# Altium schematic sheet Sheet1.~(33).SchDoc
size A3; SheetNumber: 1; SheetTotal: 1
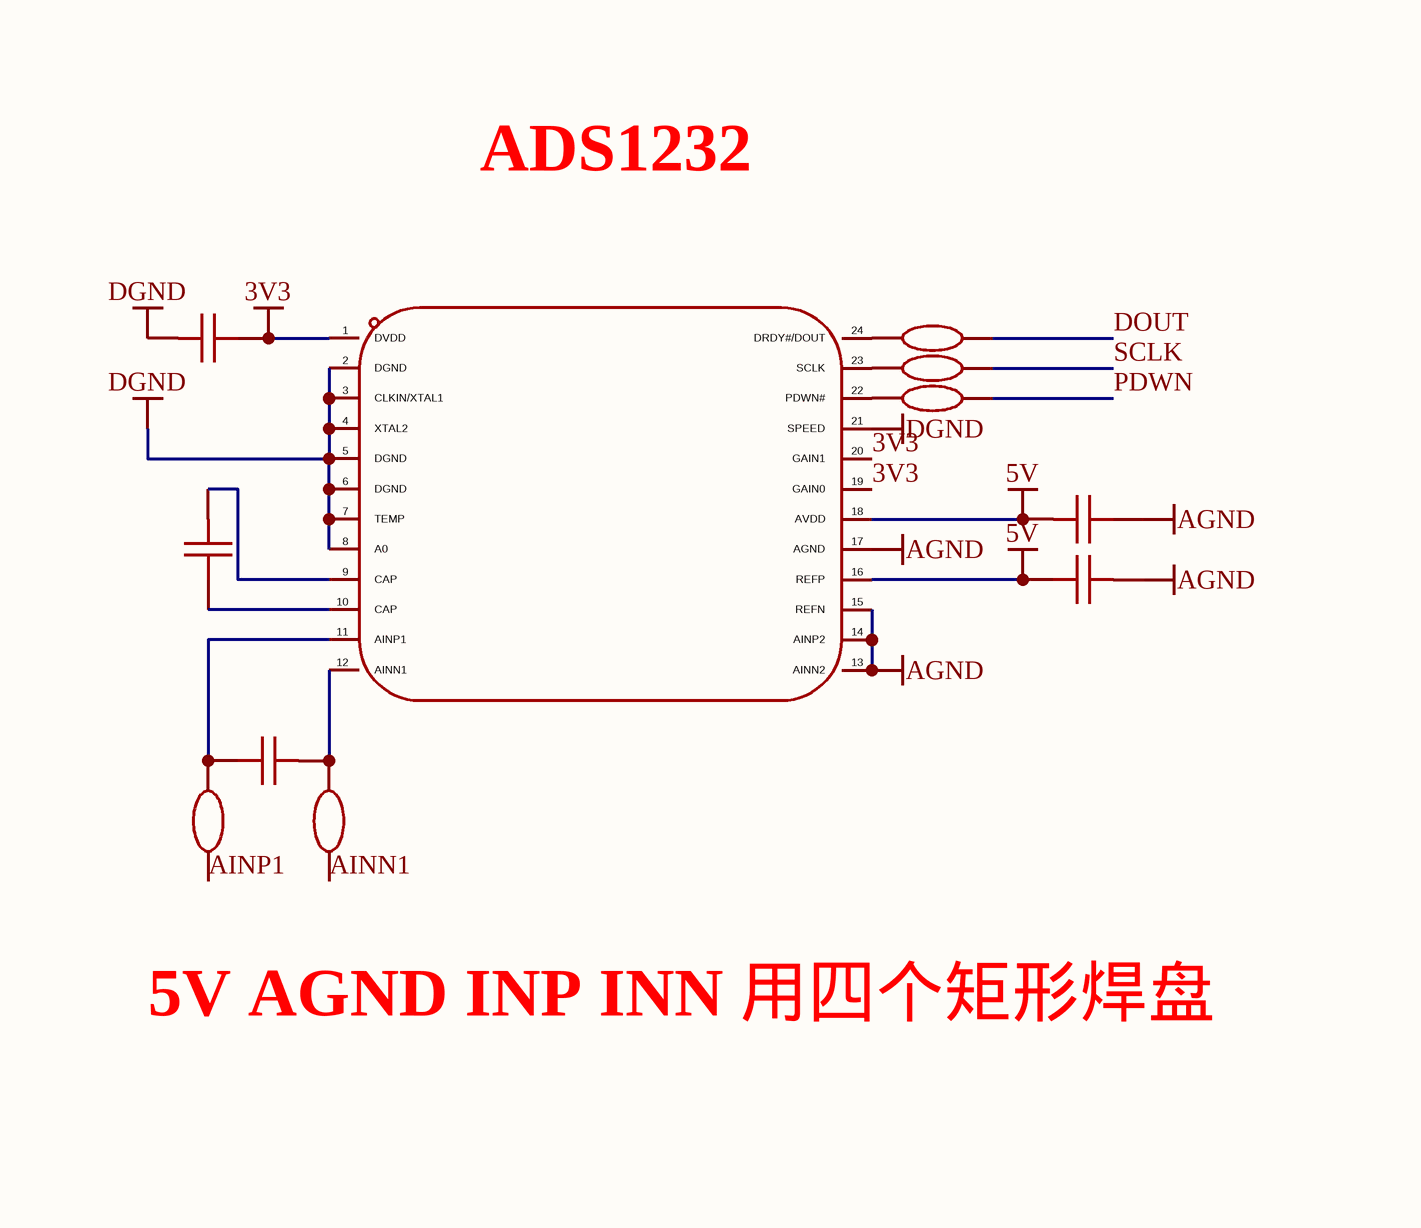
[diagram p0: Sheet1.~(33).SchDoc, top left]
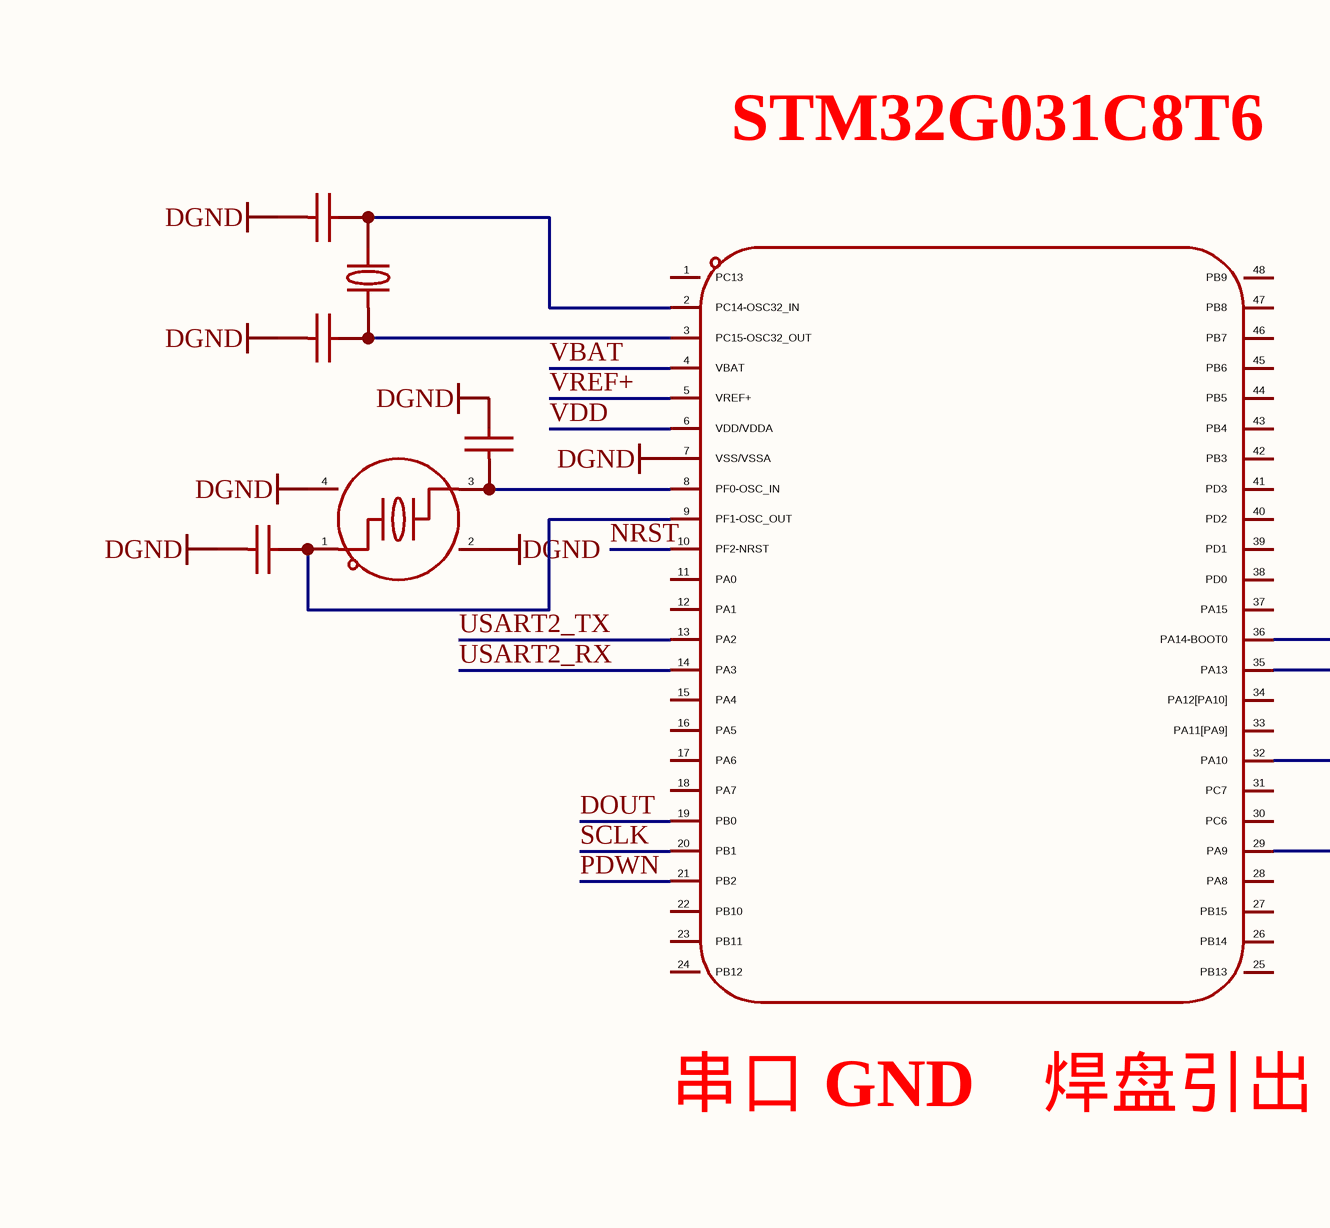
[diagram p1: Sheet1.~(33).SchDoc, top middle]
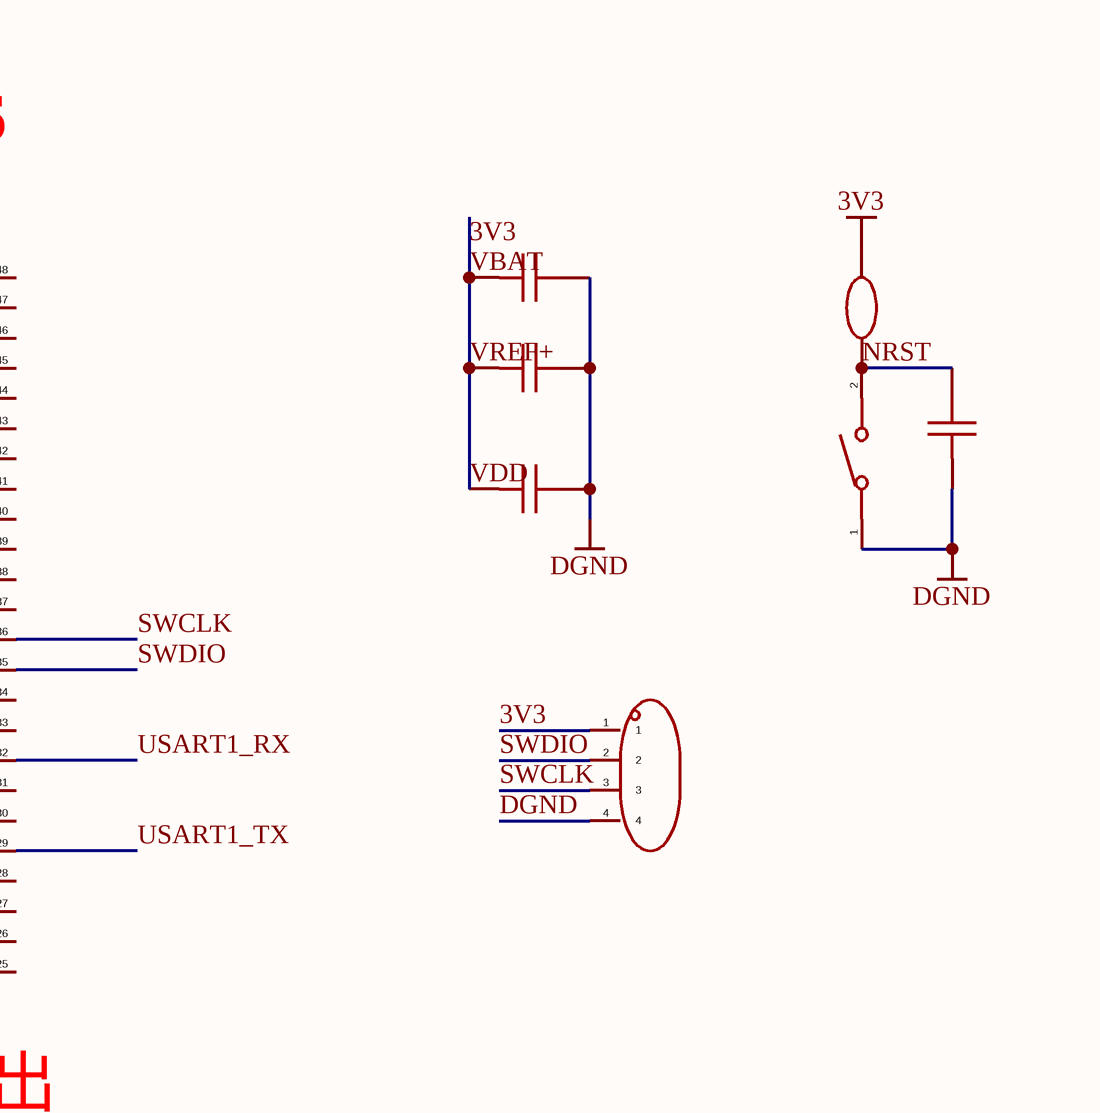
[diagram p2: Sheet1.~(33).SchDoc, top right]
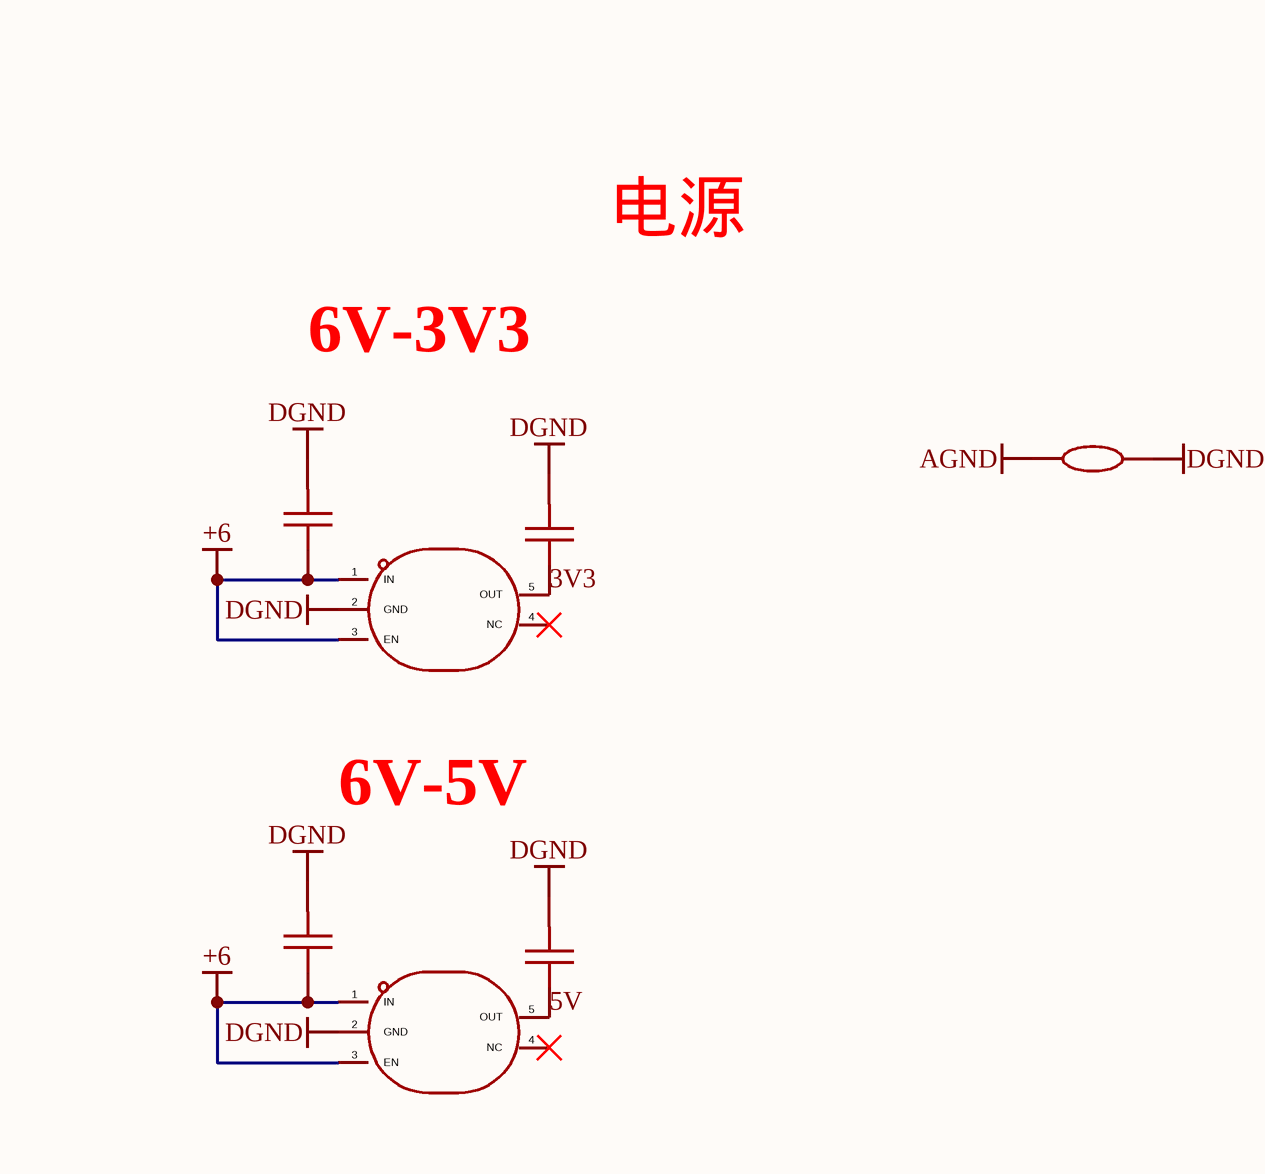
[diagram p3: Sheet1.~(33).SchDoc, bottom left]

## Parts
(Parts that share a designator on the sheet are numbered #1, #2 ... from top to bottom, then left to right.)
C?#1  cga0603x7r104k500jt  [C0603]  (value not drawn)
C?#2  cga0603x7r104k500jt  [C0603]  (value not drawn)
C?#3  cga0603x7r104k500jt  [C0603]  (value not drawn)
C?#4  cga0603x7r104k500jt  [C0603]  (value not drawn)
C?#5  cga0603x7r104k500jt  [C0603]  (value not drawn)
C?#6  cga0603x7r104k500jt  [C0603]  (value not drawn)
C?#7  fcc0603b103k500ct  [C0603]  (value not drawn)
C?#8  cga0603x5r105k500jt  [C0603]  (value not drawn)
C?#9  cga0603x5r105k500jt  [C0603]  (value not drawn)
C??#1  cc0402jrnpo9bn220  [C0402]  (value not drawn)
C??#2  cc0402jrnpo9bn220  [C0402]  (value not drawn)
C??#3  cc0402jrnpo9bn180  [C0402]  (value not drawn)
C??#4  cga0603x7r104k500jt  [C0603]  (value not drawn)
C??#5  cc0402jrnpo9bn180  [C0402]  (value not drawn)
C??#6  fcc0603b103k500ct  [C0603]  (value not drawn)
C??#7  cga0603x5r105k500jt  [C0603]  (value not drawn)
C??#8  cga0603x5r105k500jt  [C0603]  (value not drawn)
R?  0603waf470jt5e  [R0603]  (value not drawn)
R??#1  frc0603f1002ts  [R0603]  (value not drawn)
R??#2  0603waf470jt5e  [R0603]  (value not drawn)
R??#3  0603waf470jt5e  [R0603]  (value not drawn)
R??#4  frc0603f1000ts  [R0603]  (value not drawn)
R??#5  frc0603f1000ts  [R0603]  (value not drawn)
R??#6  0603waf0000t5e  [R0603]  (value not drawn)
SW??  ts-1088-ar02016  [SW-SMD_L3.9-W3.0-P4.45]  (value not drawn)
U??#1  fc31m2-32.768-ntlnndtl  [CRYSTAL-SMD_L3.2-W1.5]  (value not drawn)
U??#2  ads1232ipwr  [TSSOP-24_L7.8-W4.4-P0.65-LS6.4-BL]  (value not drawn)
U??#3  stm32g031c8t6  [LQFP-48_L7.0-W7.0-P0.50-LS9.0-BL]  (value not drawn)
U??#4  hx pz2.54-1x4p zz  [HDR-TH_4P-P2.54-V-M]  (value not drawn)
U??#5  tps7a2033pdbvr  [SOT-23-5_L2.9-W1.6-P0.95-LS2.8-BR]  (value not drawn)
U??#6  tps7a2050pdbvr  [SOT-23-5_L2.9-W1.6-P0.95-LS2.8-BR]  (value not drawn)
X??  x32258mob4si  [CRYSTAL-SMD_4P-L3.2-W2.5-BL]  (value not drawn)

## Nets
3V3: C?#1.2 C?#2.1 C?#3.2 C?#5.2 C?#8.1 R??#1.2 U??#2.1(DVDD) U??#2.19(GAIN0) U??#2.20(GAIN1) U??#3.4(VBAT) U??#3.5(VREF+) U??#3.6(VDD/VDDA) U??#4.1 U??#5.5(OUT)  [also labelled VBAT, VDD, VREF+]
5V: C?#6.2 C?#7.1 C?#9.1 U??#2.16(REFP) U??#2.18(AVDD) U??#6.5(OUT)
+6: C??#7.1 C??#8.1 U??#5.1(IN) U??#5.3(EN) U??#6.1(IN) U??#6.3(EN)
AGND: C?#6.1 C?#7.2 R??#6.1 U??#2.13(AINN2) U??#2.14(AINP2) U??#2.15(REFN) U??#2.17(AGND)
DGND: C?#1.1 C?#2.2 C?#3.1 C?#4.2 C?#5.1 C?#8.2 C?#9.2 C??#1.1 C??#2.1 C??#3.2 C??#5.1 C??#7.2 C??#8.2 R??#6.2 SW??.1 U??#2.2(DGND) U??#2.3(CLKIN/XTAL1) U??#2.4(XTAL2) U??#2.5(DGND) U??#2.6(DGND) U??#2.7(TEMP) U??#2.8(A0) U??#2.21(SPEED) U??#3.7(VSS/VSSA) U??#4.4 U??#5.2(GND) U??#6.2(GND) X??.2(GND) X??.4(GND)
AINN1: R??#5.1
AINP1: R??#4.1
DOUT: R??#2.2 U??#3.19(PB0)
NRST: C?#4.1 R??#1.1 SW??.2 U??#3.10(PF2-NRST)
PDWN: R??#3.2 U??#3.21(PB2)
SCLK: R?.2 U??#3.20(PB1)
SWCLK: U??#3.36(PA14-BOOT0) U??#4.3
SWDIO: U??#3.35(PA13) U??#4.2
USART1_RX: U??#3.32(PA10)
USART1_TX: U??#3.29(PA9)
USART2_RX: U??#3.14(PA3)
USART2_TX: U??#3.13(PA2)
NetC??#1_2: C??#1.2 U??#1.2 U??#3.2(PC14-OSC32_IN)
NetC??#2_2: C??#2.2 U??#1.1 U??#3.3(PC15-OSC32_OUT)
NetC??#3_1: C??#3.1 U??#3.8(PF0-OSC_IN) X??.3
NetC??#4_1: C??#4.1 U??#2.10(CAP)
NetC??#4_2: C??#4.2 U??#2.9(CAP)
NetC??#5_2: C??#5.2 U??#3.9(PF1-OSC_OUT) X??.1
NetC??#6_1: C??#6.1 R??#4.2 U??#2.11(AINP1)
NetC??#6_2: C??#6.2 R??#5.2 U??#2.12(AINN1)
NetR??#2_1: R??#2.1 U??#2.24(DRDY#/DOUT)
NetR??#3_1: R??#3.1 U??#2.22(PDWN#)
NetR?_1: R?.1 U??#2.23(SCLK)

Not connected (* = marked no-connect by the designer): U??#3 1(PC13) 11(PA0) 12(PA1) 15(PA4) 16(PA5) 17(PA6) 18(PA7) 22(PB10) 23(PB11) 24(PB12) 25(PB13) 26(PB14) 27(PB15) 28(PA8) 30(PC6) 31(PC7) 33(PA11[PA9]) 34(PA12[PA10]) 37(PA15) 38(PD0) 39(PD1) 40(PD2) 41(PD3) 42(PB3) 43(PB4) 44(PB5) 45(PB6) 46(PB7) 47(PB8) 48(PB9); U??#5 4(NC)*; U??#6 4(NC)*

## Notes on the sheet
- ADS1232
- STM32G031C8T6
- (near R??#4) 5V AGND INP INN 用四个矩形焊盘
- (near U??#3) 串口 GND　焊盘引出
- 电源
- 6V-3V3
- 6V-5V

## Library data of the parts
C?#1-C?#6 C??#4 = cga0603x7r104k500jt: 容值:100nF;精度:±10%;额定电压:50V;温度系数:X7R;; Manufacturer: HRE(芯声); AddInBom: yes; ModelId: ac125912035d415993ca9572d50418b1; ModelName: C0603_L1.6-W0.8-H0.8; ModelTransform: 62.992,31.496,0,0,0,0,0,0,0; Value: 100nF; Tolerance: ±10%; Voltage Rating: 50V; Temperature Coefficient: X7R
C?#7 C??#6 = fcc0603b103k500ct: 容值:10nF;精度:±10%;额定电压:50V;温度系数:X7R;; Manufacturer: FOJAN(富捷); AddInBom: yes; ModelId: ac125912035d415993ca9572d50418b1; ModelName: C0603_L1.6-W0.8-H0.8; ModelTransform: 62.992,31.496,0,0,0,0,0,0,0; Value: 10nF; Tolerance: ±10%; Voltage Rating: 50V; Temperature Coefficient: X7R
C?#8 C?#9 C??#7 C??#8 = cga0603x5r105k500jt: 容值:1uF;精度:±10%;额定电压:50V;温度系数:X5R;; Manufacturer: HRE(芯声); AddInBom: yes; ModelId: ac125912035d415993ca9572d50418b1; ModelName: C0603_L1.6-W0.8-H0.8; ModelTransform: 62.992,31.496,0,0,0,0,0,0,0; Value: 1uF; Tolerance: ±10%; Voltage Rating: 50V; Temperature Coefficient: X5R
C??#1 C??#2 = cc0402jrnpo9bn220: 容值:22pF;精度:±5%;额定电压:50V;温度系数:NP0;; Manufacturer: YAGEO(国巨); AddInBom: yes; ModelId: 36a51122f27c49738f86b3bfa98863e0; ModelName: C0402_L1.0-W0.5-H0.5; ModelTransform: 39.37,19.685,0,0,0,0,0,0,0; Value: 22pF; Tolerance: ±5%; Voltage Rating: 50V; Temperature Coefficient: NP0
C??#3 C??#5 = cc0402jrnpo9bn180: 容值:18pF;精度:±5%;额定电压:50V;温度系数:NP0;; Manufacturer: YAGEO(国巨); AddInBom: yes; ModelId: 36a51122f27c49738f86b3bfa98863e0; ModelName: C0402_L1.0-W0.5-H0.5; ModelTransform: 39.37,19.685,0,0,0,0,0,0,0; Value: 18pF; Tolerance: ±5%; Voltage Rating: 50V; Temperature Coefficient: NP0
R? R??#2 R??#3 = 0603waf470jt5e: 电阻类型:厚膜电阻;阻值:47Ω;精度:±1%;功率:100mW;工作电压:75V;温度系数:±100ppm/℃;; Manufacturer: UNI-ROYAL(厚声); AddInBom: yes; ModelId: fc143cca1e79419f9cd78b61e9279f08; ModelTransform: 31.8897,63.7794,0,90,0,0,0,0,0; Value: 47Ω; Tolerance: ±1%; Power(Watts): 100mW; Voltage-Supply(Max): 75V
R??#1 = frc0603f1002ts: 电阻类型:厚膜电阻;阻值:10kΩ;精度:±1%;功率:100mW;工作电压:75V;温度系数:±100ppm/℃;; Manufacturer: FOJAN(富捷); AddInBom: yes; ModelId: fc143cca1e79419f9cd78b61e9279f08; ModelTransform: 31.8897,63.7794,0,90,0,0,0,0,0; Value: 10kΩ; Tolerance: ±1%; Power(Watts): 100mW; Voltage-Supply(Max): 75V
R??#4 R??#5 = frc0603f1000ts: 电阻类型:厚膜电阻;阻值:100Ω;精度:±1%;功率:100mW;工作电压:75V;温度系数:±100ppm/℃;; Manufacturer: FOJAN(富捷); AddInBom: yes; ModelId: fc143cca1e79419f9cd78b61e9279f08; ModelTransform: 31.8897,63.7794,0,90,0,0,0,0,0; Value: 100Ω; Tolerance: ±1%; Power(Watts): 100mW; Voltage-Supply(Max): 75V
R??#6 = 0603waf0000t5e: 电阻类型:厚膜电阻;阻值:0Ω;精度:±1%;功率:100mW;工作电压:75V;温度系数:-;; Manufacturer: UNI-ROYAL(厚声); AddInBom: yes; ModelId: fc143cca1e79419f9cd78b61e9279f08; ModelTransform: 31.8897,63.7794,0,90,0,0,0,0,0; Value: 0Ω; Tolerance: ±1%; Power(Watts): 100mW; Voltage-Supply(Max): 75V
SW?? = ts-1088-ar02016: 电路结构:单刀单掷;按钮形状:圆形按钮;作用力:1.6N;安装方式:立贴;开关长度:3.9mm;开关宽度:3mm;开关高度:2mm;带支架:不带支架;触点电流:50mA;额定电压:12V;带灯:-;工作寿命:10万次;; Manufacturer: XUNPU(讯普); AddInBom: yes; ModelId: b26698b69f274ffabef8a26c7d0e5dd1; ModelName: SW-SMD_L3.9-W2.9-H2.0-LS4.8; ModelTransform: 188.976,114.174,0,0,0,0,0,0,0; Circuit: 单刀单掷; Actuator Style: 圆形按钮; Operating Force: 1.6N; Switch Height: 2mm; with Bracket: 不带支架; Contact Current: 50mA; Voltage Rating: 12V; Actuator/Cap Color: 黑色; Life: 10万次
U??#1 = fc31m2-32.768-ntlnndtl: 晶振类型:贴片晶振;频率:32.768kHz;常温频差:±10ppm;负载电容:12.5pF;频率稳定度:±10ppm;; Manufacturer: HCI(杭晶); AddInBom: yes; ModelId: 762d7afc596f4558a373612390f4386d; ModelName: CRYSTAL-SMD_L3.2-W1.5-1; ModelTransform: 125.984,59.055,0,0,0,0,0,0,0; Normal temperature Frequency Tolerance: ±10ppm; Load Capacitance: 12.5pF; Equivalent Series Resistance(ESR): 70kΩ
U??#2 = ads1232ipwr: 分辨率(位):24;采样率:10Hz;工作电压:2.7V~5.3V;接口类型:SPI;; Manufacturer: TI(德州仪器); AddInBom: yes; ModelId: 57e278220af748a2882c4abba4094eb9; ModelName: TSSOP-24_L7.8-W4.4-H1.0-LS6.4-P0.65; ModelTransform: 252.188,307.086,0,90,0,0,0,0,0; Resolution (Bits): 24; Sampling Rate: 10Hz; number of channels: 2; Interface: SPI; differential input: 是; Clock/Oscillator: 内置；外置; Clock Frequency: 4.9152MHz；200kHz~8MHz; Voltage Reference: 外置; Programmable Gain: 支持; Temperature Sensors: 内置; ADC architecture: Sigma-Delta; Data rate: 80Hz；10Hz; Quiescent Current (Iq): 1.3uA; Full-Scale Range(FSR): 39mV；1.25V；19.5mV；2.5V
U??#3 = stm32g031c8t6: CPU内核:ARM Cortex-M0+;CPU最大主频:64MHz;CPU位数:32 Bit;; Manufacturer: ST(意法半导体); AddInBom: yes; ModelId: 093be70396ff421eb2cdb946d5311efc; ModelName: LQFP-48_L7.0-W7.0-H1.4-LS9.0-P0.50; ModelTransform: 354.331,354.331,0,0,0,0,0,0,0; CPU Maximum Speed: 64MHz; Core Size: 32 Bit; Program Storage Size: 64KB; Program Memory Type: FLASH; RAM Size: 8KB; Number of I/O: 44; ADC (Bit): 12bit; Oscillator Type: 内置+外置; Voltage - Supply: 1.7V~3.6V
U??#4 = hx pz2.54-1x4p zz: 插针结构:1x4P;间距:2.54mm;行距:-;圆针/方针:方针;安装方式:直插;排数:单排;总PIN位数:4P;额定电流:3A;额定电压:1kV;配合针长度:6mm;塑高:2.5mm;端接针长度:3mm;触头材质:黄铜;触头镀层:金;工作温度:-40℃~+105℃;颜色:黑色;; Manufacturer: hanxia(韩下); AddInBom: yes; ModelId: 112f4d05e8d64e99ab9a333894bea4f9; ModelName: HDR-TH_4P-P2.54-M-LI-1X4P; ModelTransform: 399.999,104.7242,0,0,0,0,0,0,-118.11; Pin Structure: 1x4P; Pitch: 2.54mm; Circluar Pins/Square Pins: 方针; Current Rating: 3A; Voltage Rating (Max): 1kV
U??#5 = tps7a2033pdbvr: 输出类型:固定;最大输入电压:6V;输出电压:3.3V;输出电流:300mA;输出极性:正极;; Manufacturer: TI(德州仪器); AddInBom: yes; ModelId: 7ba65df16e7b4570af156e925f9c37fe; ModelTransform: 114.173,114.173,0,90,0,0,0,0,0; Output Type: 固定; Maximum Input Voltage: 6V; Output Voltage: 3.3V; Output Current: 300mA; Dropout Voltage: 140mV@(300mA); standby current: 15uA; Output Polarity: 正极; Number of Outputs: 1
U??#6 = tps7a2050pdbvr: 输出极性:正极;工作电压:6V;输出电压:5V;输出电流:300mA;电源纹波抑制比(PSRR):65dB@(100Hz);输出类型:固定;; Manufacturer: TI(德州仪器); AddInBom: yes; ModelId: 7ba65df16e7b4570af156e925f9c37fe; ModelTransform: 114.173,114.173,0,90,0,0,0,0,0; Output Configuration: 正极; Voltage - Supply: 6V; Output Voltage: 5V; Output Current: 300mA; Voltage Dropout: 140mV@(300mA); standby current: 6.5uA; Noise: 10uVrms; Output Type: 固定; Number of Outputs: 1
X?? = x32258mob4si: 晶振类型:贴片晶振;频率:8MHz;常温频差:±10ppm;负载电容:12pF;频率稳定度:±20ppm;; Manufacturer: YXC(扬兴晶振); AddInBom: yes; ModelId: ff2dfd5650294453a14147960efe1838; ModelTransform: 125.984,98.425,0,0,0,0,0,0,0; Value: 8MHz; Normal temperature Frequency Tolerance: ±10ppm; Load Capacitance: 12pF; Frequency Stability: ±20ppm; Equivalent Series Resistance(ESR): 180Ω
